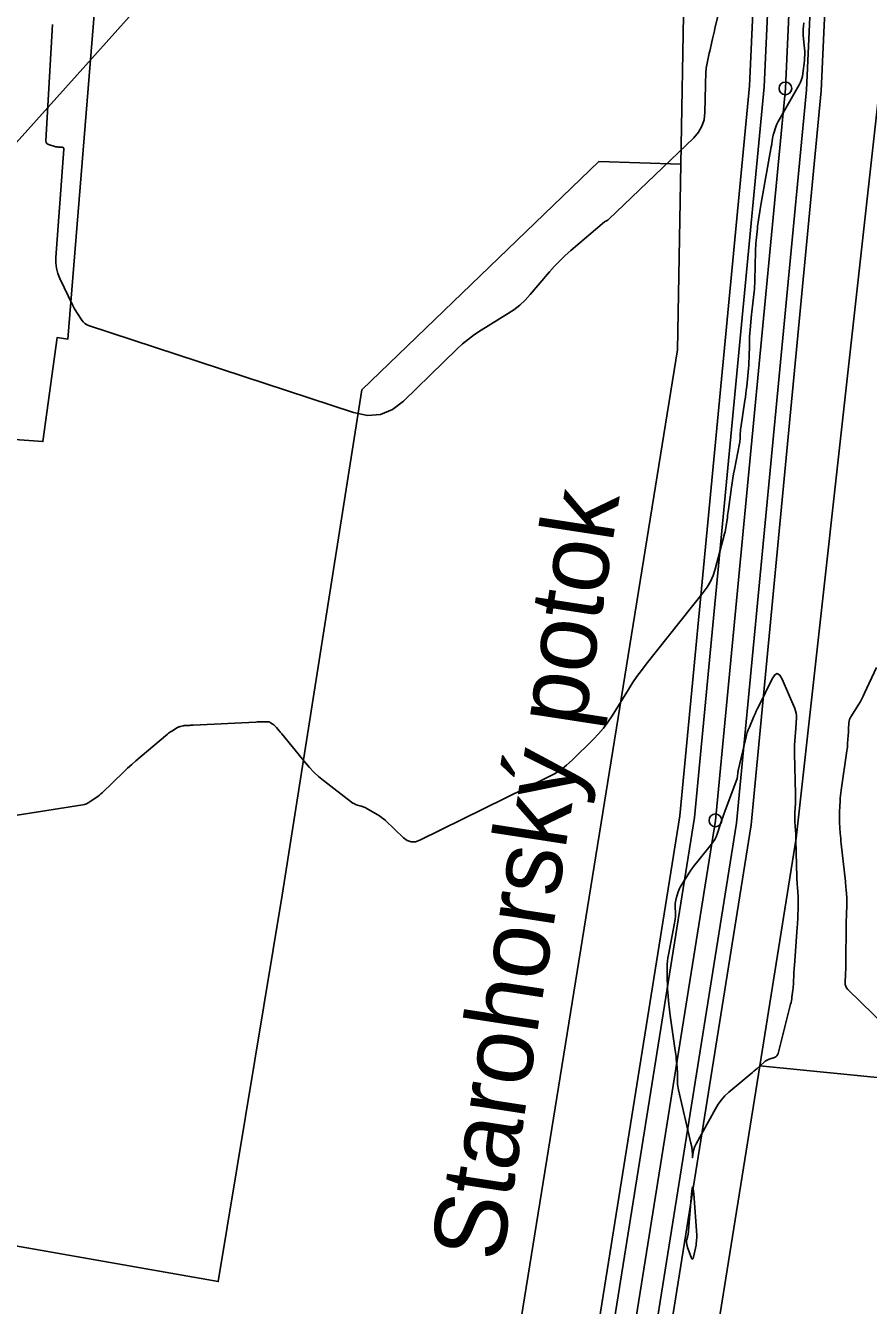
# Model space of a CAD drawing. Extents: x -534481 to -534262, y -1190577 to -1190138.
# Drawn here: x -534363.49 to -534343.59, y -1190312.37 to -1190282.16 of the extents above; entities that cross this region are included whole.
import ezdxf

# ---------------------------------------------------------------- set-up
doc = ezdxf.new("R2010")
doc.units = 0
for name, color, linetype in [('Bonity', 7, 'Continuous'), ('Definiční body', 7, 'Continuous'), ('Polygon parcely', 7, 'Continuous'), ('Vrstva 18', 7, 'Continuous'), ('Vrstva 19', 7, 'Continuous'), ('Vrstva 31', 7, 'Continuous'), ('Vrstva 32', 7, 'Continuous'), ('Vrstva 37', 7, 'Continuous'), ('Vrstva 47', 7, 'Continuous')]:
    doc.layers.add(name, color=color, linetype=linetype)

msp = doc.modelspace()

# ---------------------------------------------------------------- linework, layer by layer
at = {"layer": 'Bonity'}
msp.add_lwpolyline([(-534409.868, -1190391.439), (-534405.947, -1190382.816), (-534400.873, -1190377.487), (-534393.696, -1190372.718), (-534384.927, -1190365.477), (-534382.631, -1190361.148), (-534355.894, -1190347.823), (-534351.738, -1190342.389), (-534351.577, -1190328.316), (-534347.204, -1190300.921), (-534345.553, -1190283.64), (-534344.682, -1190264.494)], dxfattribs=at)
at = {"layer": 'Definiční body'}
for p, q in [((-534348.02, -1190285.43), (-534347.63, -1190264.06)), ((-534346.16, -1190306.72), (-534333.95, -1190307.91))]:
    msp.add_line(p, q, dxfattribs=at)
for points in [[(-534341.18, -1190264.8), (-534342.09, -1190272.42), (-534345.3, -1190301.34), (-534346.16, -1190306.72)], [(-534370.75, -1190309.73), (-534358.94, -1190311.81), (-534357.43, -1190302.69), (-534355.55, -1190290.76), (-534349.96, -1190285.37), (-534348.02, -1190285.43)], [(-534353.4, -1190337.34), (-534353.51, -1190323.36), (-534348.1, -1190289.81), (-534348.02, -1190285.43)], [(-534346.16, -1190306.72), (-534349.7, -1190328.83), (-534349.69, -1190337.24)]]:
    msp.add_lwpolyline(points, dxfattribs=at)
at = {"layer": 'Polygon parcely'}
msp.add_lwpolyline([(-534366.14, -1190271.54), (-534367.96, -1190291.63), (-534363.08, -1190291.98), (-534362.74, -1190289.52), (-534362.49, -1190289.56), (-534361.74, -1190280.34), (-534361.6, -1190280.35), (-534360.7, -1190271.99), (-534350.93, -1190272.19), (-534350.88, -1190263.57), (-534365.11, -1190263.3)], close=True, dxfattribs=at)
at = {"layer": 'Vrstva 18'}
for points in [[(-534345.12, -1190282.096), (-534345.129, -1190282.17), (-534345.134, -1190282.245), (-534345.134, -1190282.32), (-534345.13, -1190282.395), (-534345.102, -1190282.697), (-534345.098, -1190282.771), (-534345.097, -1190282.844), (-534345.1, -1190282.918), (-534345.106, -1190282.991), (-534345.139, -1190283.285), (-534345.151, -1190283.357), (-534345.17, -1190283.427), (-534345.196, -1190283.494), (-534345.23, -1190283.56), (-534345.704, -1190284.383), (-534345.723, -1190284.418), (-534345.74, -1190284.452), (-534345.755, -1190284.488), (-534345.768, -1190284.524), (-534345.834, -1190284.722), (-534345.838, -1190284.733), (-534345.841, -1190284.746), (-534345.844, -1190284.758), (-534345.846, -1190284.77), (-534345.856, -1190284.832), (-534345.862, -1190284.869), (-534345.875, -1190284.947), (-534345.877, -1190284.964), (-534345.88, -1190284.981), (-534345.883, -1190284.999), (-534345.886, -1190285.016), (-534346.124, -1190286.346), (-534346.133, -1190286.396), (-534346.142, -1190286.445), (-534346.15, -1190286.495), (-534346.158, -1190286.545), (-534346.189, -1190286.745), (-534346.196, -1190286.795), (-534346.203, -1190286.845), (-534346.209, -1190286.895), (-534346.214, -1190286.945), (-534346.243, -1190287.229), (-534346.249, -1190287.293), (-534346.253, -1190287.358), (-534346.257, -1190287.422), (-534346.259, -1190287.486), (-534346.274, -1190288.176), (-534346.277, -1190288.243), (-534346.281, -1190288.31), (-534346.286, -1190288.377), (-534346.293, -1190288.444), (-534346.325, -1190288.711), (-534346.333, -1190288.778), (-534346.341, -1190288.845), (-534346.347, -1190288.912), (-534346.354, -1190288.979), (-534346.386, -1190289.338), (-534346.392, -1190289.42), (-534346.398, -1190289.502), (-534346.402, -1190289.585), (-534346.404, -1190289.667), (-534346.411, -1190290.006), (-534346.413, -1190290.09), (-534346.418, -1190290.173), (-534346.424, -1190290.257), (-534346.432, -1190290.341), (-534346.467, -1190290.677), (-534346.476, -1190290.761), (-534346.486, -1190290.844), (-534346.497, -1190290.928), (-534346.509, -1190291.011), (-534346.607, -1190291.656), (-534346.611, -1190291.687), (-534346.614, -1190291.717), (-534346.616, -1190291.748), (-534346.618, -1190291.779), (-534346.622, -1190291.902), (-534346.624, -1190291.933), (-534346.627, -1190291.963), (-534346.631, -1190291.994), (-534346.636, -1190292.024), (-534346.758, -1190292.638), (-534346.778, -1190292.742), (-534346.796, -1190292.845), (-534346.812, -1190292.949), (-534346.827, -1190293.053), (-534346.897, -1190293.582), (-534346.903, -1190293.63), (-534346.91, -1190293.678), (-534346.916, -1190293.726), (-534346.923, -1190293.775), (-534346.949, -1190293.967), (-534346.956, -1190294.015), (-534346.965, -1190294.063), (-534346.976, -1190294.111), (-534346.987, -1190294.158), (-534347.21, -1190294.988), (-534347.258, -1190295.138), (-534347.321, -1190295.281), (-534347.399, -1190295.417), (-534347.491, -1190295.545), (-534348.84, -1190297.237), (-534348.951, -1190297.381), (-534349.058, -1190297.527), (-534349.16, -1190297.677), (-534349.258, -1190297.83), (-534349.644, -1190298.456), (-534349.742, -1190298.604), (-534349.847, -1190298.744), (-534349.961, -1190298.878), (-534350.083, -1190299.005), (-534350.587, -1190299.501), (-534350.717, -1190299.619), (-534350.856, -1190299.725), (-534351.002, -1190299.821), (-534351.157, -1190299.904), (-534354.182, -1190301.392), (-534354.286, -1190301.427), (-534354.385, -1190301.429), (-534354.478, -1190301.398), (-534354.567, -1190301.333), (-534354.996, -1190300.928), (-534355.041, -1190300.887), (-534355.088, -1190300.85), (-534355.137, -1190300.816), (-534355.188, -1190300.784), (-534355.449, -1190300.636), (-534355.476, -1190300.621), (-534355.504, -1190300.608), (-534355.533, -1190300.596), (-534355.563, -1190300.586), (-534355.683, -1190300.551), (-534355.712, -1190300.54), (-534355.74, -1190300.527), (-534355.767, -1190300.512), (-534355.793, -1190300.494), (-534356.455, -1190299.979), (-534356.571, -1190299.883), (-534356.681, -1190299.782), (-534356.785, -1190299.675), (-534356.883, -1190299.561), (-534357.44, -1190298.882), (-534357.455, -1190298.863), (-534357.471, -1190298.844), (-534357.486, -1190298.826), (-534357.501, -1190298.807), (-534357.564, -1190298.729), (-534357.578, -1190298.712), (-534357.594, -1190298.696), (-534357.612, -1190298.681), (-534357.63, -1190298.668), (-534357.705, -1190298.617), (-534357.725, -1190298.606), (-534357.745, -1190298.598), (-534357.766, -1190298.594), (-534357.789, -1190298.593), (-534357.928, -1190298.596), (-534357.959, -1190298.597), (-534357.99, -1190298.598), (-534358.021, -1190298.599), (-534358.052, -1190298.601), (-534359.533, -1190298.675), (-534359.554, -1190298.676), (-534359.575, -1190298.676), (-534359.596, -1190298.677), (-534359.617, -1190298.678), (-534359.71, -1190298.68), (-534359.726, -1190298.681), (-534359.743, -1190298.683), (-534359.759, -1190298.686), (-534359.776, -1190298.689), (-534359.84, -1190298.706), (-534359.856, -1190298.711), (-534359.872, -1190298.717), (-534359.887, -1190298.724), (-534359.902, -1190298.732), (-534360.038, -1190298.812), (-534360.065, -1190298.829), (-534360.092, -1190298.847), (-534360.117, -1190298.866), (-534360.142, -1190298.886), (-534360.786, -1190299.431), (-534360.885, -1190299.517), (-534360.984, -1190299.604), (-534361.08, -1190299.693), (-534361.176, -1190299.784), (-534361.677, -1190300.268), (-534361.711, -1190300.299), (-534361.746, -1190300.329), (-534361.782, -1190300.357), (-534361.819, -1190300.384), (-534361.972, -1190300.487), (-534362.011, -1190300.511), (-534362.052, -1190300.53), (-534362.095, -1190300.544), (-534362.14, -1190300.554), (-534363.689, -1190300.8)], [(-534341.953, -1190306.983), (-534344.077, -1190304.912), (-534344.107, -1190304.876), (-534344.128, -1190304.837), (-534344.139, -1190304.794), (-534344.142, -1190304.748), (-534344.133, -1190304.555), (-534344.131, -1190304.507), (-534344.13, -1190304.459), (-534344.129, -1190304.41), (-534344.128, -1190304.362), (-534344.116, -1190303.309), (-534344.115, -1190303.262), (-534344.114, -1190303.216), (-534344.113, -1190303.17), (-534344.111, -1190303.123), (-534344.103, -1190302.937), (-534344.102, -1190302.891), (-534344.102, -1190302.845), (-534344.103, -1190302.798), (-534344.106, -1190302.752), (-534344.12, -1190302.557), (-534344.123, -1190302.509), (-534344.127, -1190302.461), (-534344.132, -1190302.413), (-534344.137, -1190302.366), (-534344.236, -1190301.477), (-534344.243, -1190301.414), (-534344.248, -1190301.351), (-534344.254, -1190301.288), (-534344.258, -1190301.225), (-534344.275, -1190300.971), (-534344.278, -1190300.908), (-534344.279, -1190300.844), (-534344.279, -1190300.781), (-534344.276, -1190300.718), (-534344.262, -1190300.461), (-534344.258, -1190300.397), (-534344.252, -1190300.333), (-534344.245, -1190300.269), (-534344.237, -1190300.206), (-534344.102, -1190299.277), (-534344.096, -1190299.234), (-534344.091, -1190299.191), (-534344.087, -1190299.148), (-534344.084, -1190299.104), (-534344.072, -1190298.921), (-534344.067, -1190298.844), (-534344.062, -1190298.768), (-534344.053, -1190298.616), (-534344.048, -1190298.579), (-534344.039, -1190298.543), (-534344.025, -1190298.508), (-534344.007, -1190298.475), (-534343.819, -1190298.175), (-534343.782, -1190298.113), (-534343.747, -1190298.051), (-534343.714, -1190297.987), (-534343.684, -1190297.922), (-534343.405, -1190297.311)]]:
    msp.add_lwpolyline(points, dxfattribs=at)
at = {"layer": 'Vrstva 19'}
msp.add_lwpolyline([(-534362.849, -1190282.132), (-534363.008, -1190284.876), (-534363.006, -1190284.907), (-534362.995, -1190284.932), (-534362.976, -1190284.951), (-534362.948, -1190284.964), (-534362.795, -1190285.011), (-534362.774, -1190285.016), (-534362.753, -1190285.02), (-534362.732, -1190285.023), (-534362.711, -1190285.025), (-534362.625, -1190285.028), (-534362.606, -1190285.032), (-534362.593, -1190285.04), (-534362.586, -1190285.054), (-534362.585, -1190285.073), (-534362.772, -1190287.63), (-534362.773, -1190287.76), (-534362.758, -1190287.887), (-534362.726, -1190288.01), (-534362.677, -1190288.131), (-534362.379, -1190288.748), (-534362.355, -1190288.796), (-534362.33, -1190288.843), (-534362.303, -1190288.889), (-534362.275, -1190288.934), (-534362.16, -1190289.114), (-534362.128, -1190289.155), (-534362.091, -1190289.189), (-534362.049, -1190289.217), (-534362.001, -1190289.237), (-534355.744, -1190291.294), (-534355.419, -1190291.36), (-534355.114, -1190291.337), (-534354.829, -1190291.224), (-534354.566, -1190291.022), (-534353.306, -1190289.795), (-534353.173, -1190289.672), (-534353.034, -1190289.557), (-534352.888, -1190289.45), (-534352.736, -1190289.351), (-534352.109, -1190288.966), (-534351.963, -1190288.868), (-534351.825, -1190288.759), (-534351.697, -1190288.64), (-534351.578, -1190288.51), (-534351.119, -1190287.968), (-534351.002, -1190287.836), (-534350.879, -1190287.708), (-534350.752, -1190287.586), (-534350.619, -1190287.468), (-534349.821, -1190286.792), (-534349.814, -1190286.786), (-534349.807, -1190286.781), (-534349.799, -1190286.776), (-534349.791, -1190286.772), (-534349.759, -1190286.756), (-534349.751, -1190286.752), (-534349.744, -1190286.747), (-534349.737, -1190286.742), (-534349.73, -1190286.736), (-534347.714, -1190284.804), (-534347.603, -1190284.677), (-534347.522, -1190284.535), (-534347.472, -1190284.38), (-534347.452, -1190284.212), (-534347.428, -1190283.243), (-534347.426, -1190283.202), (-534347.422, -1190283.162), (-534347.417, -1190283.122), (-534347.409, -1190283.082), (-534347.375, -1190282.924), (-534347.366, -1190282.884), (-534347.358, -1190282.845), (-534347.349, -1190282.805), (-534347.34, -1190282.765), (-534347.274, -1190282.471), (-534347.26, -1190282.409), (-534347.245, -1190282.347), (-534347.23, -1190282.285), (-534347.215, -1190282.223), (-534347.09, -1190281.712)], dxfattribs=at)
for points in [[(-534347.696, -1190308.637), (-534347.722, -1190308.717), (-534347.738, -1190308.8), (-534347.743, -1190308.886), (-534347.746, -1190308.799), (-534347.753, -1190308.713), (-534347.765, -1190308.627), (-534347.783, -1190308.543), (-534348.078, -1190307.286), (-534348.087, -1190307.243), (-534348.093, -1190307.199), (-534348.097, -1190307.155), (-534348.099, -1190307.111), (-534348.1, -1190306.933), (-534348.101, -1190306.889), (-534348.103, -1190306.845), (-534348.105, -1190306.8), (-534348.109, -1190306.756), (-534348.128, -1190306.549), (-534348.133, -1190306.5), (-534348.139, -1190306.451), (-534348.145, -1190306.402), (-534348.152, -1190306.353), (-534348.274, -1190305.532), (-534348.283, -1190305.464), (-534348.292, -1190305.395), (-534348.299, -1190305.326), (-534348.305, -1190305.258), (-534348.328, -1190304.982), (-534348.333, -1190304.913), (-534348.336, -1190304.844), (-534348.339, -1190304.775), (-534348.34, -1190304.706), (-534348.343, -1190304.393), (-534348.342, -1190304.318), (-534348.337, -1190304.244), (-534348.328, -1190304.17), (-534348.315, -1190304.096), (-534348.169, -1190303.35), (-534348.16, -1190303.3), (-534348.154, -1190303.25), (-534348.151, -1190303.2), (-534348.15, -1190303.149), (-534348.153, -1190302.927), (-534348.152, -1190302.886), (-534348.148, -1190302.845), (-534348.141, -1190302.805), (-534348.131, -1190302.766), (-534348.083, -1190302.608), (-534348.069, -1190302.569), (-534348.054, -1190302.531), (-534348.035, -1190302.495), (-534348.014, -1190302.459), (-534347.822, -1190302.159), (-534347.782, -1190302.098), (-534347.74, -1190302.038), (-534347.696, -1190301.979), (-534347.651, -1190301.922), (-534347.299, -1190301.487), (-534347.257, -1190301.431), (-534347.221, -1190301.372), (-534347.19, -1190301.309), (-534347.165, -1190301.244), (-534347.075, -1190300.978), (-534347.052, -1190300.911), (-534347.029, -1190300.845), (-534347.005, -1190300.779), (-534346.981, -1190300.713), (-534346.694, -1190299.935), (-534346.689, -1190299.92), (-534346.685, -1190299.905), (-534346.682, -1190299.889), (-534346.681, -1190299.873), (-534346.677, -1190299.809), (-534346.676, -1190299.793), (-534346.674, -1190299.777), (-534346.671, -1190299.761), (-534346.668, -1190299.745), (-534346.489, -1190298.977), (-534346.472, -1190298.911), (-534346.452, -1190298.846), (-534346.43, -1190298.783), (-534346.404, -1190298.72), (-534346.296, -1190298.47), (-534346.269, -1190298.408), (-534346.241, -1190298.346), (-534346.212, -1190298.284), (-534346.183, -1190298.223), (-534345.868, -1190297.582), (-534345.806, -1190297.487), (-534345.746, -1190297.457), (-534345.688, -1190297.49), (-534345.631, -1190297.588), (-534345.332, -1190298.283), (-534345.313, -1190298.336), (-534345.3, -1190298.391), (-534345.294, -1190298.446), (-534345.294, -1190298.502), (-534345.31, -1190298.744), (-534345.316, -1190298.844), (-534345.323, -1190298.945), (-534345.336, -1190299.145), (-534345.338, -1190299.195), (-534345.34, -1190299.246), (-534345.34, -1190299.296), (-534345.339, -1190299.346), (-534345.314, -1190300.305), (-534345.313, -1190300.359), (-534345.314, -1190300.413), (-534345.315, -1190300.467), (-534345.317, -1190300.521), (-534345.329, -1190300.737), (-534345.331, -1190300.791), (-534345.332, -1190300.844), (-534345.331, -1190300.898), (-534345.328, -1190300.952), (-534345.314, -1190301.172), (-534345.31, -1190301.226), (-534345.308, -1190301.281), (-534345.305, -1190301.336), (-534345.304, -1190301.39), (-534345.282, -1190302.264), (-534345.28, -1190302.322), (-534345.278, -1190302.38), (-534345.274, -1190302.438), (-534345.271, -1190302.496), (-534345.254, -1190302.728), (-534345.251, -1190302.786), (-534345.249, -1190302.845), (-534345.249, -1190302.903), (-534345.251, -1190302.961), (-534345.261, -1190303.203), (-534345.263, -1190303.262), (-534345.267, -1190303.322), (-534345.27, -1190303.382), (-534345.274, -1190303.441), (-534345.342, -1190304.352), (-534345.345, -1190304.401), (-534345.348, -1190304.451), (-534345.351, -1190304.5), (-534345.354, -1190304.549), (-534345.363, -1190304.76), (-534345.365, -1190304.802), (-534345.368, -1190304.844), (-534345.372, -1190304.886), (-534345.377, -1190304.928), (-534345.399, -1190305.095), (-534345.405, -1190305.136), (-534345.412, -1190305.178), (-534345.42, -1190305.219), (-534345.43, -1190305.26), (-534345.726, -1190306.429), (-534345.738, -1190306.459), (-534345.755, -1190306.484), (-534345.779, -1190306.504), (-534345.808, -1190306.517), (-534345.939, -1190306.561), (-534345.971, -1190306.574), (-534346.001, -1190306.589), (-534346.029, -1190306.608), (-534346.056, -1190306.629), (-534346.222, -1190306.779), (-534346.259, -1190306.812), (-534346.295, -1190306.844), (-534346.332, -1190306.876), (-534346.37, -1190306.907), (-534346.886, -1190307.34), (-534346.98, -1190307.426), (-534347.064, -1190307.52), (-534347.14, -1190307.621), (-534347.206, -1190307.73), (-534347.66, -1190308.559)], [(-534347.734, -1190311.269), (-534347.746, -1190311.281), (-534347.76, -1190311.271), (-534347.776, -1190311.238), (-534347.862, -1190311.005), (-534347.867, -1190310.99), (-534347.872, -1190310.974), (-534347.875, -1190310.958), (-534347.878, -1190310.942), (-534347.887, -1190310.874), (-534347.888, -1190310.859), (-534347.888, -1190310.845), (-534347.886, -1190310.831), (-534347.882, -1190310.817), (-534347.864, -1190310.761), (-534347.86, -1190310.747), (-534347.857, -1190310.732), (-534347.854, -1190310.718), (-534347.852, -1190310.703), (-534347.771, -1190309.739), (-534347.757, -1190309.615), (-534347.744, -1190309.574), (-534347.73, -1190309.615), (-534347.717, -1190309.739), (-534347.64, -1190310.713), (-534347.64, -1190310.727), (-534347.64, -1190310.74), (-534347.64, -1190310.753), (-534347.641, -1190310.766), (-534347.648, -1190310.834), (-534347.651, -1190310.855), (-534347.656, -1190310.909), (-534347.657, -1190310.919), (-534347.658, -1190310.93), (-534347.66, -1190310.94), (-534347.662, -1190310.951), (-534347.723, -1190311.235)]]:
    msp.add_lwpolyline(points, close=True, dxfattribs=at)
at = {"layer": 'Vrstva 31'}
msp.add_lwpolyline([(-534409.732, -1190388.64), (-534397.101, -1190322.153), (-534346.296, -1190265.502)], dxfattribs=at)
at = {"layer": 'Vrstva 32'}
for points in [[(-534409.97, -1190389.61), (-534406.662, -1190382.333), (-534401.423, -1190376.832), (-534394.204, -1190372.034), (-534385.599, -1190364.929), (-534383.254, -1190360.509), (-534356.45, -1190347.15), (-534352.584, -1190342.096), (-534352.426, -1190328.244), (-534348.048, -1190300.813), (-534346.401, -1190283.581), (-534345.607, -1190266.12)], [(-534409.916, -1190390.337), (-534406.368, -1190382.532), (-534401.196, -1190377.102), (-534393.995, -1190372.316), (-534385.322, -1190365.155), (-534382.997, -1190360.772), (-534356.221, -1190347.427), (-534352.236, -1190342.217), (-534352.076, -1190328.274), (-534347.7, -1190300.857), (-534346.052, -1190283.605), (-534345.255, -1190266.096)], [(-534409.363, -1190391.537), (-534405.527, -1190383.099), (-534400.549, -1190377.873), (-534393.398, -1190373.12), (-534384.532, -1190365.799), (-534382.264, -1190361.524), (-534355.568, -1190348.219), (-534351.24, -1190342.56), (-534351.077, -1190328.359), (-534346.708, -1190300.984), (-534345.054, -1190283.675), (-534344.256, -1190266.142)], [(-534409.02, -1190391.627), (-534405.233, -1190383.298), (-534400.323, -1190378.142), (-534393.189, -1190373.401), (-534384.256, -1190366.025), (-534382.008, -1190361.787), (-534355.339, -1190348.496), (-534350.891, -1190342.681), (-534350.728, -1190328.388), (-534346.36, -1190301.028), (-534344.705, -1190283.7), (-534343.908, -1190266.201)]]:
    msp.add_lwpolyline(points, dxfattribs=at)
at = {"layer": 'Vrstva 37'}
for centre in [(-534345.553, -1190283.64), (-534345.553, -1190283.64), (-534345.553, -1190283.64), (-534345.553, -1190283.64), (-534345.553, -1190283.64), (-534345.553, -1190283.64), (-534347.204, -1190300.921), (-534347.204, -1190300.921), (-534347.204, -1190300.921), (-534347.204, -1190300.921), (-534347.204, -1190300.921), (-534347.204, -1190300.921)]:
    msp.add_circle(centre, 0.15, dxfattribs=at)

# ---------------------------------------------------------------- texts
at = {"layer": 'Vrstva 47'}
msp.add_text('Starohorský potok', height=1.7, rotation=81.2569, dxfattribs=at).set_placement((-534352.248, -1190311.375))

doc.saveas('drawing.dxf')
